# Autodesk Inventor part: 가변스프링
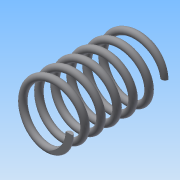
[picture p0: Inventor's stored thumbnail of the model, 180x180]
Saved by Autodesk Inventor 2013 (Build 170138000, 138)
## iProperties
Created: 2016-09
Part Number: 가변스프링
Material: 일반
Document SubType Name: Modeling
Designer: Administrator
Density: 1 g/cm^3
Author: Administrator
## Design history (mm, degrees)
sketch "스케치1"
  geometry: L1 (0, 0)-(8, 0); L2 (8, 0)-(8, 28.5); L3 (8, 28.5)-(0, 28.5); L4 (0, 28.5)-(0, 0); C1 r 1 at (8, 0)
  constraints: 8 end point, 2 parallel, 1 centre point, 1 coincident, 1 horizontal, 1 perpendicular
  dimensions: "d0" = 2 diameter of C1; "d3" = 16 diameter of L2 L4; "d4" = 28.5 distance of L1.end L2.end (derived)
feature "코일1" sketch "스케치1" pitch "d5" = 10; turns "d7" = 6; dims "d6" = 28.5 (= d4), "d8" = 0, angle "d9" = 90 deg, angle "d10" = 90 deg, "d11" = 0, "d12" = 0
sketch "스케치2"
  geometry: L1 (-9, 0)-(-7, 0) reference; 1 further point
  constraints: 1 horizontal alignment
extrude "돌출1" cut sketch "스케치2" distance "d13" = 10; taper "d14" = 0 deg
node "작업 평면1"
sketch "스케치3"
  geometry: L1 (1, 0)-(-1, 0) reference; 1 further point
  constraints: 1 horizontal alignment
extrude "돌출2" cut sketch "스케치3" distance "d16" = 10; taper "d17" = 0 deg
node "솔리드1"
node "절단 모서리 투영1"
node "절단 모서리 투영2"
other parameters: "d15" = 0
